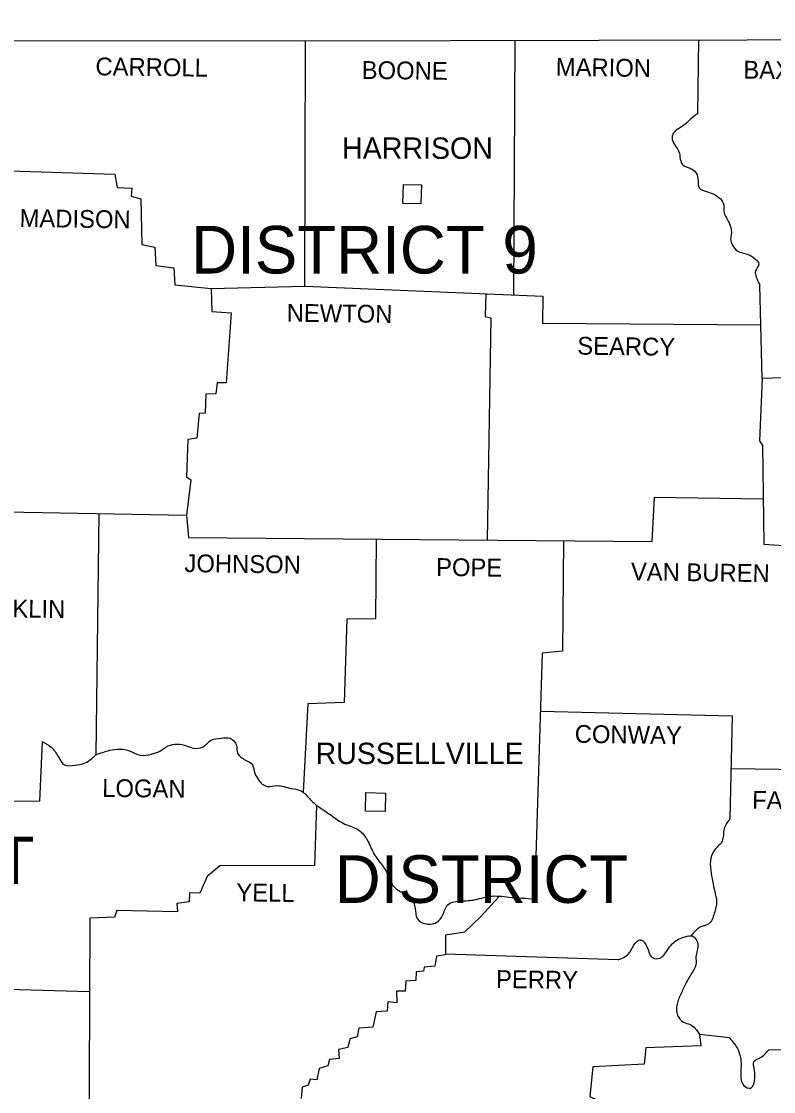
# Model space of a CAD drawing. Extents: x -0.25 to 1.42, y 0 to 0.92.
# Drawn here: x 1.1381 to 1.2203, y 0.703 to 0.8199 of the extents above; entities that cross this region are included whole.
import ezdxf

# ---------------------------------------------------------------- set-up
doc = ezdxf.new("R2010")
doc.units = 0
doc.layers.add('SHET_Annotations', color=7, linetype='Continuous')

msp = doc.modelspace()

# ---------------------------------------------------------------- linework, layer by layer
at = {"layer": 'SHET_Annotations'}
msp.add_line((1.2115, 0.7202), (1.21134, 0.72002), dxfattribs=at)
for points in [[(1.09511, 0.81784), (1.16886, 0.81779), (1.23365, 0.81792), (1.31002, 0.81909), (1.34545, 0.81992)], [(1.13684, 0.80359), (1.14835, 0.80321), (1.14861, 0.80176), (1.15019, 0.80171), (1.15014, 0.80083), (1.1512, 0.80054), (1.1513, 0.79554), (1.15273, 0.79523), (1.15283, 0.79325), (1.15481, 0.793), (1.15491, 0.79115), (1.15886, 0.79073), (1.16912, 0.791), (1.1692, 0.81779)], [(1.19208, 0.81784), (1.19192, 0.79004)], [(1.21215, 0.81788), (1.21204, 0.80983)], [(1.23362, 0.81792), (1.23372, 0.80679), (1.23297, 0.80674), (1.23308, 0.79538), (1.22991, 0.79491), (1.23017, 0.79188), (1.23126, 0.79045), (1.23118, 0.78685), (1.22498, 0.78662), (1.22475, 0.78107), (1.2191, 0.78088), (1.21879, 0.77409), (1.21912, 0.77357), (1.21928, 0.76278), (1.229, 0.76213), (1.22887, 0.73809), (1.23665, 0.73789), (1.23665, 0.7134), (1.23053, 0.71294), (1.23009, 0.70759), (1.2198, 0.70752)], [(1.09854, 0.79022), (1.10724, 0.79019), (1.10745, 0.79318), (1.11059, 0.79318), (1.11087, 0.79805), (1.12869, 0.79743), (1.12921, 0.79878), (1.13672, 0.79894), (1.13289, 0.78825), (1.13214, 0.77131), (1.13159, 0.77129), (1.13134, 0.76618), (1.13401, 0.76595), (1.13442, 0.76636), (1.15618, 0.76595), (1.15641, 0.76353)], [(1.15886, 0.79073), (1.15896, 0.7882), (1.16106, 0.78809), (1.16051, 0.78042), (1.15955, 0.78044), (1.15937, 0.77922), (1.15828, 0.7792), (1.15823, 0.77712), (1.15755, 0.77707), (1.15732, 0.77437), (1.15631, 0.77424), (1.15618, 0.77015), (1.15665, 0.76981), (1.15618, 0.76595)], [(1.16912, 0.791), (1.19511, 0.78991), (1.19508, 0.78693), (1.21895, 0.78677)], [(1.2191, 0.78088), (1.21884, 0.79113)], [(1.18889, 0.79017), (1.18881, 0.78768), (1.18943, 0.78752), (1.18904, 0.76325)], [(1.15641, 0.76353), (1.20706, 0.76309), (1.20732, 0.76792), (1.21921, 0.76776)], [(1.14661, 0.76613), (1.14627, 0.73978)], [(1.1769, 0.76336), (1.17685, 0.75464), (1.17371, 0.75459), (1.17343, 0.74551), (1.16943, 0.74535), (1.16895, 0.73569)], [(1.19737, 0.76318), (1.19729, 0.75109), (1.19506, 0.75088), (1.19423, 0.72404)], [(1.19486, 0.74455), (1.21583, 0.74403), (1.21557, 0.73278)], [(1.14041, 0.74123), (1.1401, 0.73472), (1.13416, 0.73467), (1.13382, 0.72873), (1.12796, 0.72889), (1.12778, 0.72279), (1.12161, 0.72271), (1.1214, 0.71659), (1.12532, 0.71639), (1.12516, 0.71449), (1.14558, 0.71393)], [(1.2157, 0.7383), (1.22887, 0.73809)], [(1.17039, 0.73425), (1.17018, 0.72769), (1.15981, 0.72764), (1.15844, 0.72647), (1.15763, 0.72466), (1.15652, 0.72471), (1.15647, 0.7237), (1.15514, 0.72354), (1.15519, 0.72261), (1.14858, 0.72277), (1.14832, 0.72204), (1.1456, 0.72194), (1.14552, 0.69525), (1.14321, 0.6952), (1.14342, 0.69385), (1.14122, 0.69387), (1.14116, 0.69286), (1.13901, 0.69286), (1.13906, 0.69216), (1.1359, 0.69206), (1.13582, 0.68928), (1.13274, 0.68957), (1.13222, 0.66711)], [(1.19037, 0.7243), (1.18831, 0.72209), (1.18655, 0.72041), (1.18447, 0.72007), (1.1845, 0.71792), (1.18349, 0.71779), (1.18331, 0.7167), (1.18214, 0.71659), (1.18209, 0.71613), (1.18128, 0.71607), (1.18126, 0.71511), (1.18014, 0.71506), (1.18007, 0.71397), (1.17913, 0.71397), (1.17918, 0.71268), (1.1782, 0.71278), (1.17812, 0.71177), (1.1769, 0.71169), (1.17656, 0.71003), (1.17501, 0.7099), (1.17485, 0.70897), (1.17402, 0.70876), (1.17382, 0.7078), (1.17278, 0.70759), (1.17286, 0.70661), (1.17182, 0.7065), (1.17164, 0.70578), (1.17068, 0.70552), (1.17044, 0.70427), (1.16969, 0.70435), (1.16948, 0.7037), (1.16881, 0.70347), (1.16873, 0.70223)], [(1.20335, 0.71737), (1.1845, 0.718)], [(1.21552, 0.70884), (1.21225, 0.70923), (1.21238, 0.70798), (1.20639, 0.70775), (1.20621, 0.70599), (1.20058, 0.70567), (1.20027, 0.70246), (1.2011, 0.70204), (1.2011, 0.69994)]]:
    msp.add_lwpolyline(points, dxfattribs=at)
for points in [[(1.17983, 0.80002), (1.17988, 0.8021), (1.18186, 0.80205), (1.1818, 0.79997)], [(1.17573, 0.73363), (1.17579, 0.73565), (1.17794, 0.7356), (1.17789, 0.73358)]]:
    msp.add_lwpolyline(points, close=True, dxfattribs=at)
for points in [[(1.21204, 0.80983), (1.21121, 0.80918), (1.21051, 0.80853), (1.2094, 0.80773), (1.20927, 0.807), (1.20963, 0.8063), (1.20999, 0.8057), (1.21015, 0.80487), (1.21046, 0.8042), (1.21121, 0.80389), (1.21189, 0.80332), (1.21209, 0.80251), (1.2122, 0.80174), (1.2129, 0.80137), (1.21373, 0.80106), (1.21453, 0.80052), (1.2149, 0.79987), (1.21495, 0.79896), (1.21528, 0.79831), (1.21565, 0.79746), (1.21573, 0.79678), (1.21565, 0.79611), (1.21585, 0.79546), (1.21643, 0.79481), (1.21746, 0.7945), (1.21821, 0.79406), (1.21873, 0.79341), (1.21837, 0.79266), (1.21845, 0.79196), (1.21884, 0.79113)], [(1.14627, 0.73978), (1.1478, 0.74027), (1.14889, 0.7404), (1.15001, 0.74019), (1.15115, 0.73973), (1.15234, 0.73986), (1.15325, 0.74017), (1.15418, 0.74076), (1.15517, 0.74095), (1.15615, 0.74076), (1.15717, 0.74048), (1.15823, 0.74082), (1.15888, 0.74139), (1.15997, 0.74159), (1.16095, 0.74159), (1.16163, 0.74082), (1.16176, 0.73996), (1.16264, 0.73921), (1.16339, 0.73869), (1.16365, 0.73776), (1.16404, 0.73706), (1.16445, 0.73659), (1.16505, 0.73633), (1.16606, 0.73641), (1.16762, 0.7361), (1.1686, 0.73589), (1.16954, 0.73508), (1.17039, 0.73425)], [(1.14041, 0.74123), (1.1414, 0.74061), (1.14218, 0.73957), (1.14285, 0.73869), (1.14402, 0.73864), (1.14492, 0.73882), (1.14627, 0.73978)], [(1.17039, 0.73425), (1.172, 0.73317), (1.1735, 0.73221), (1.17503, 0.73153), (1.17589, 0.73055), (1.17667, 0.72896), (1.17734, 0.728), (1.17812, 0.72681), (1.17874, 0.72551), (1.17968, 0.72476), (1.18069, 0.72414), (1.18118, 0.723), (1.18141, 0.72186), (1.18253, 0.72129), (1.18359, 0.72152), (1.18416, 0.72222), (1.18473, 0.72339), (1.18595, 0.72378), (1.18753, 0.72391), (1.18935, 0.72432), (1.1914, 0.72424), (1.19423, 0.72404)], [(1.21557, 0.73278), (1.21495, 0.73171), (1.21471, 0.73034), (1.21396, 0.72946), (1.21349, 0.7285), (1.21347, 0.72715), (1.21368, 0.72596), (1.21391, 0.72484), (1.21412, 0.72378), (1.21386, 0.72245), (1.21326, 0.72131), (1.21238, 0.72098), (1.2115, 0.7202)], [(1.20335, 0.71737), (1.20447, 0.71802), (1.20507, 0.71898), (1.20579, 0.71958), (1.20652, 0.71875), (1.20717, 0.71758), (1.20787, 0.71755), (1.20872, 0.71841), (1.20927, 0.71913), (1.20997, 0.71965), (1.21069, 0.71991), (1.21145, 0.71999), (1.21207, 0.71911), (1.21186, 0.71773), (1.21186, 0.71685), (1.21137, 0.71587), (1.2108, 0.71486), (1.21023, 0.71371), (1.20979, 0.71252), (1.20986, 0.7113), (1.21051, 0.71055), (1.21121, 0.71032), (1.21225, 0.70923)], [(1.21552, 0.70884), (1.2163, 0.70785), (1.21676, 0.70648), (1.21676, 0.70492), (1.2171, 0.70365), (1.21785, 0.70337), (1.21829, 0.70448), (1.21821, 0.70555), (1.21819, 0.70622), (1.21899, 0.70676), (1.2198, 0.70752)]]:
    msp.add_spline(points, degree=3, dxfattribs=at)

# ---------------------------------------------------------------- texts
for s, rotation, p in [('CARROLL', 359.267, (1.14622, 0.81403)), ('BOONE', 359.3139, (1.17532, 0.81364)), ('MARION', 359.2237, (1.19653, 0.81398)), ('BAXTER', 359.2892, (1.21703, 0.81367)), ('MADISON', 359.217, (1.13793, 0.79746)), ('NEWTON', 359.303, (1.16712, 0.78711)), ('SEARCY', 359.2838, (1.19888, 0.78351)), ('JOHNSON', 359.2575, (1.15595, 0.75975)), ('POPE', 359.3389, (1.18345, 0.75933)), ('VAN BUREN', 359.2547, (1.20474, 0.75884)), ('FRANKLIN', 359.1782, (1.13006, 0.7549)), ('CONWAY', 359.1737, (1.1986, 0.7411)), ('LOGAN', 359.3076, (1.14696, 0.73519)), ('FAULKNER', 359.2447, (1.21799, 0.73389)), ('YELL', 359.3097, (1.16162, 0.72378)), ('PERRY', 359.2992, (1.19, 0.71431))]:
    msp.add_text(s, height=0.001945, rotation=rotation, dxfattribs=at).set_placement(p)
for s, height, p in [('HARRISON', 0.002334, (1.17319, 0.8049)), ('DISTRICT 9', 0.005203, (1.15669, 0.79237)), ('RUSSELLVILLE', 0.0023341, (1.17029, 0.73877)), ('DISTRICT', 0.005203, (1.10749, 0.72565)), ('DISTRICT', 0.005203, (1.17238, 0.7236))]:
    msp.add_text(s, height=height, dxfattribs=at).set_placement(p)

doc.saveas('drawing.dxf')
